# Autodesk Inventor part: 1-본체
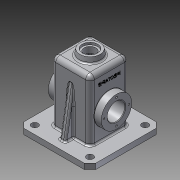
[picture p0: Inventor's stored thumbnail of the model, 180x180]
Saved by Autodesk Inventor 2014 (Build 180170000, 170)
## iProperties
Created: 2016-02
Part Number: 1-본체
Material: 알루미늄 6061
Document SubType Name: Modeling
Designer: S. S. MOON
Density: 2.71 g/cm^3
Appearance: 알루미늄 - 평지
Mass: 934.098 g
Surface Area: 1041.9 cm^2
Volume: 344.686 cm^3
Author: S. S. MOON
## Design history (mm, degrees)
sketch "스케치1"
  geometry: C1 r 27.5 at (0, 0); 1 further point
  constraints: 1 centre point, 1 coincident
  dimensions: "d0" = 55 diameter of C1
extrude "돌출1" new body sketch "스케치1" stored distance "d1" = 96; taper "d2" = 0 deg
sketch "스케치2"
  geometry: L1 (-35, 35)-(35, 35); L2 (35, 35)-(35, -35); L3 (35, -35)-(-35, -35); L4 (-35, -35)-(-35, 35); 3 further points
  constraints: 8 end point, 2 midpoint, 2 parallel, 1 horizontal, 1 horizontal alignment, 1 perpendicular, 1 vertical alignment
  dimensions: "d3" = 70 distance of L1.start L1.end; "d4" = 70 distance of L3.end L1.start
extrude "돌출2" join sketch "스케치2" distance "d5" = 55; taper "d6" = 0 deg
extrude "돌출3" join sketch "스케치2" distance "d7" = 65; taper "d8" = 0 deg
sketch "스케치3"
  geometry: C1 r 20 at (0, 0); 1 further point
  constraints: 1 centre point, 1 coincident
  dimensions: "d9" = 40 diameter of C1
extrude "돌출4" join sketch "스케치3" distance "d10" = 10; taper "d11" = -10 deg
sketch "스케치13"
  geometry: L1 (65, -65)-(-65, -65); L2 (-65, -65)-(-65, 65); L3 (-65, 65)-(65, 65); L4 (65, 65)-(65, -65); 3 further points
  constraints: 8 end point, 2 midpoint, 2 parallel, 1 horizontal, 1 horizontal alignment, 1 perpendicular, 1 vertical alignment
  dimensions: "d20" = 130 distance of L1.start L1.end; "d21" = 130 distance of L3.end L1.start
extrude "돌출7" join sketch "스케치13" distance "d22" = 10; taper "d23" = 0 deg
sketch "스케치14"
  geometry: L1 (-35, -45)-(35, -45) reference; L2 (35, -45)-(35, 65) reference; L3 (-35, 65)-(35, 65) reference; L4 (-35, 65)-(-35, -45) reference; L5 (-65, -55)-(65, -55) reference; L6 (30, 60)-(30, -55); L7 (-30, -55)-(-30, 60); L8 (-30, 60)-(30, 60); 1 further point
  constraints: 6 end point, 2 point on line, 1 vertical, 1 other
  dimensions: "d25" = 5 distance between parallel lines of L4 L7; "d26" = 5 distance between parallel lines of L2 L6
extrude "돌출8" cut sketch "스케치14" stored distance "d27" = 60; taper "d28" = 0 deg
sketch "스케치15"
  geometry: L1 (23, -27.5)-(30, -27.5); L2 (30, -27.5)-(30, 0); L3 (30, 0)-(23, 0); L4 (23, 0)-(23, -27.5); L5 (48, -27.5)-(35, -27.5) reference; L6 (30, -55)-(30, 60) reference; L7 (30, -27.5)-(23, -20.5); 2 further points
  constraints: 10 end point, 2 collinear, 2 parallel, 1 horizontal, 1 horizontal alignment, 1 midpoint, 1 perpendicular, 1 point on line
  dimensions: "d30" = 7 distance between parallel lines of L4 L2; "d31" = 135 deg angle of L6 L7
revolve "회전1" sketch "스케치15" stored, may be unused: angle "d32" = 90 deg
hole "구멍1" diameter "d35" = 21; stored, may be unused: countersink angle "d39" = 90 deg, drill point angle "d41" = 118 deg; dims "d36" = 6, "d37" = 28, "d38" = 4, "d40" = 21, "d95" = 10, "d96" = 10
hole "구멍2" diameter "d44" = 32; stored, may be unused: countersink angle "d48" = 90 deg, drill point angle "d50" = 118 deg; dims "d42" = 10, "d43" = 10, "d45" = 6, "d46" = 25, "d47" = 4, "d49" = 21
sketch "스케치16"
  geometry: L1 (0, 0)-(-22.5, 0)
  constraints: 2 end point, 1 horizontal
  dimensions: "d51" = 22.5 distance of L1.start L1.end
hole "구멍3" sketch "스케치16" at (0, 0), (-22.5, 0) diameter "d52" = 3.242; stored, may be unused: countersink angle "d56" = 90 deg, drill point angle "d58" = 118 deg; dims "d53" = 8, "d54" = 25, "d55" = 4, "d57" = 10
sketch "스케치17"
  geometry: L1 (-50, -50)-(50, -50); L2 (50, -50)-(50, 50); L3 (50, 50)-(-50, 50); L4 (-50, 50)-(-50, -50); 3 further points
  constraints: 8 end point, 2 midpoint, 2 parallel, 1 horizontal, 1 horizontal alignment, 1 perpendicular, 1 vertical alignment
  dimensions: "d62" = 100 distance of L3.end L1.start; "d63" = 100 distance of L1.start L1.end
hole "구멍4" sketch "스케치17" at (-50, -50), (50, 50), (50, -50), (-50, 50) diameter "d64" = 12; stored, may be unused: countersink angle "d68" = 90 deg, drill point angle "d70" = 118 deg; dims "d65" = 12, "d66" = 25, "d67" = 4, "d69" = 10
sketch "스케치18"
  geometry: L1 (-50, -45)-(-35, 40.069); L2 (-35, 65)-(-35, -45) reference; L3 (-56, -45)-(-44, -45) reference; L4 (65, -45)-(-65, -45) reference; L5 (-65, -55)-(-65, -45) reference; 1 further point
  constraints: 2 end point, 2 point on line
  dimensions: "d71" = 15 distance from line of L5 L1.start; "d72" = 10 deg angle of L5 L1
extrude "돌출9" join sketch "스케치18" stored distance "d73" = 10; taper "d74" = 0 deg
fillet "모깎기1" dims "d75" = 0.5
fillet "모깎기2" dims "d76" = 3
fillet "모깎기3" dims "d77" = 3
fillet "모깎기4" dims "d78" = 3
chamfer "모따기1" distance "d80" = 1; stored, may be unused: second distance "d81" = 2, angle "d82" = 45 deg
chamfer "모따기2" distance "d83" = 10; stored, may be unused: second distance "d84" = 2, angle "d85" = 45 deg
fillet "모깎기7" dims "d87" = 8
fillet "모깎기8" dims "d88" = 8
fillet "모깎기9" dims "d89" = 0.5
fillet "모깎기10" dims "d90" = 3
fillet "모깎기11" dims "d91" = 3
fillet "모깎기12" dims "d92" = 3
fillet "모깎기13" dims "d93" = 3
fillet "모깎기14" dims "d94" = 3
sketch "스케치19"
  geometry: L1 (99, 62)-(0, 62) reference; L2 (21.916, 5.803)-(21.916, 48.197); L3 (21.916, 48.197)-(2.084, 48.197); L4 (2.084, 48.197)-(2.084, 5.803); L5 (2.084, 5.803)-(21.916, 5.803); L6 (-18, 8.763)-(-18, 45.237) reference; 3 further points
  constraints: 2 midpoint, 1 horizontal, 2 other
  dimensions: "d98" = 35 distance from line of L1 point (21.916, 27); "d99" = 30 distance from line of L6 point (12, 5.803)
feature "엠보싱1" sketch "스케치19" dims "d0" = 55, "d100" = 0.5, "d101" = 0
node "솔리드1"
mirror "대칭1"
pattern_circular "원형 패턴1" dims angle "d60" = 360 deg
mirror "대칭2"
mirror "대칭3"
node "투영된 루프2"
